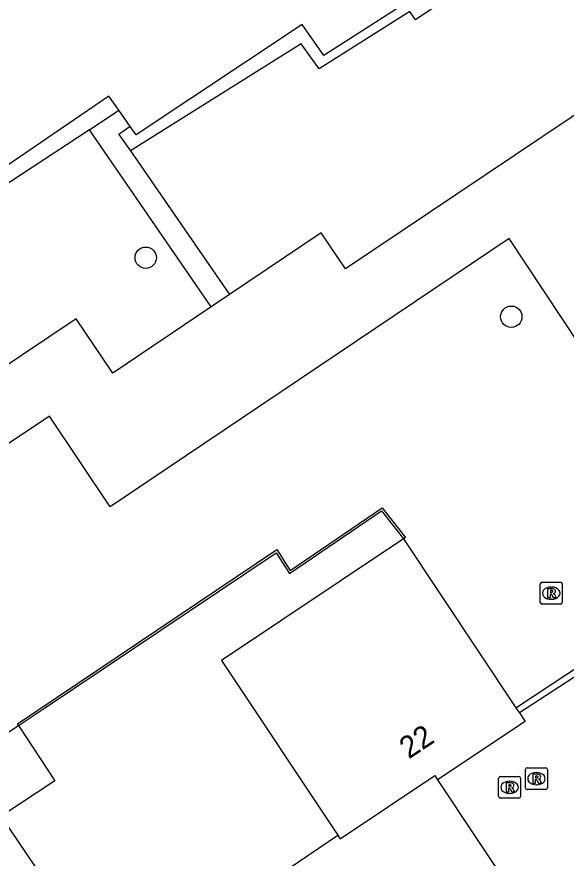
# Model space of a CAD drawing. Extents: x 158797 to 159887, y 384318 to 385255.
# Drawn here: x 158949.74 to 158974.86, y 384566.6 to 384605.03 of the extents above; entities that cross this region are included whole.
import ezdxf

# ---------------------------------------------------------------- set-up
doc = ezdxf.new("R2010")
doc.units = 0
for name, color, linetype in [('IMGEO_Boom', 7, 'Continuous'), ('IMGEO_Haag', 7, 'Continuous'), ('IMGEO_Hek', 7, 'Continuous'), ('IMGEO_Pand', 7, 'Continuous'), ('IMGEO_Pand_nummerreeks', 7, 'Continuous'), ('IMGEO_Rioolput', 7, 'Continuous'), ('IMGEO_Voetpad_gesloten', 7, 'Continuous'), ('IMGEO_Voetpad_open', 7, 'Continuous')]:
    doc.layers.add(name, color=color, linetype=linetype)

msp = doc.modelspace()

# ---------------------------------------------------------------- linework, layer by layer
at = {"layer": 'IMGEO_Boom'}
for centre in [(158955.638, 384594.028), (158972.345, 384591.33)]:
    msp.add_circle(centre, 0.489, dxfattribs=at)
at = {"layer": 'IMGEO_Haag'}
for points in [[(158967.471, 384605.617), (158963.772, 384603.26), (158962.785, 384604.676), (158955.192, 384599.646), (158954.921, 384600.028)], [(158967.706, 384605.269), (158963.564, 384602.657), (158962.736, 384603.801), (158954.947, 384598.907)], [(158954.401, 384600.762), (158953.943, 384601.409), (158945.185, 384595.438), (158944.644, 384596.144)], [(158953.064, 384599.873), (158944.835, 384594.486)], [(158949.825, 384572.659), (158949.77, 384572.742), (158961.624, 384580.694), (158962.235, 384579.747), (158966.437, 384582.607), (158967.504, 384581.247), (158967.425, 384581.185)], [(158949.825, 384572.659), (158951.056, 384573.478), (158961.595, 384580.554), (158962.205, 384579.606), (158966.416, 384582.472), (158967.425, 384581.185)], [(158972.561, 384573.474), (158980.537, 384578.738)], [(158980.737, 384578.44), (158972.715, 384573.244)]]:
    msp.add_lwpolyline(points, dxfattribs=at)
at = {"layer": 'IMGEO_Hek'}
msp.add_lwpolyline([(158951.056, 384573.478), (158961.595, 384580.554), (158962.205, 384579.606), (158966.416, 384582.472), (158967.425, 384581.185)], dxfattribs=at)
at = {"layer": 'IMGEO_Pand'}
for points in [[(158972.484, 384607.938), (158967.965, 384604.885), (158967.706, 384605.269)], [(158967.425, 384581.185), (158967.334, 384581.124), (158959.094, 384575.635), (158964.417, 384567.646)], [(158967.425, 384581.185), (158972.561, 384573.474)], [(158972.561, 384573.474), (158972.71, 384573.251), (158972.715, 384573.244)], [(158972.715, 384573.244), (158972.98, 384572.846), (158968.969, 384570.174)], [(158949.053, 384568.535), (158947.394, 384571.063), (158949.825, 384572.659)], [(158949.825, 384572.659), (158951.484, 384570.131), (158949.053, 384568.535)], [(158964.417, 384567.646), (158964.528, 384567.481), (158968.844, 384570.38), (158968.969, 384570.174)], [(158968.969, 384570.174), (158974.292, 384562.184)], [(158974.292, 384562.184), (158972.943, 384561.285), (158965.971, 384556.642), (158960.393, 384564.934), (158964.417, 384567.646)]]:
    msp.add_lwpolyline(points, dxfattribs=at)
at = {"layer": 'IMGEO_Rioolput'}
for p, q in [((158973.746, 384579.206), (158974.598, 384579.206)), ((158973.671, 384578.28), (158973.671, 384579.132)), ((158974.159, 384578.986), (158974.184, 384578.986)), ((158974.672, 384579.132), (158974.672, 384578.28)), ((158974.598, 384578.206), (158973.746, 384578.206)), ((158974.182, 384578.426), (158974.157, 384578.426)), ((158972.995, 384569.808), (158972.995, 384570.66)), ((158973.07, 384570.734), (158973.922, 384570.734)), ((158973.483, 384570.514), (158973.508, 384570.514)), ((158973.996, 384570.66), (158973.996, 384569.808)), ((158971.769, 384569.412), (158971.769, 384570.264)), ((158971.844, 384570.338), (158972.696, 384570.338)), ((158972.257, 384570.118), (158972.282, 384570.118)), ((158972.77, 384570.264), (158972.77, 384569.412)), ((158973.922, 384569.734), (158973.07, 384569.734)), ((158973.506, 384569.954), (158973.481, 384569.954)), ((158972.696, 384569.338), (158971.844, 384569.338)), ((158972.28, 384569.558), (158972.255, 384569.558))]:
    msp.add_line(p, q, dxfattribs=at)
for points in [[(158973.746, 384579.206), (158974.598, 384579.206)], [(158973.671, 384578.28), (158973.671, 384579.132)], [(158974.26, 384578.904), (158974.008, 384578.906), (158974.008, 384578.506)], [(158974.186, 384578.825), (158974.132, 384578.825), (158974.132, 384578.744)], [(158974.672, 384579.132), (158974.672, 384578.28)], [(158974.008, 384578.506), (158974.132, 384578.506), (158974.132, 384578.668), (158974.143, 384578.668)], [(158974.132, 384578.744), (158974.184, 384578.744)], [(158974.19, 384578.639), (158974.261, 384578.506), (158974.401, 384578.506), (158974.336, 384578.632)], [(158974.598, 384578.206), (158973.746, 384578.206)], [(158972.995, 384569.808), (158972.995, 384570.66)], [(158973.07, 384570.734), (158973.922, 384570.734)], [(158973.584, 384570.432), (158973.332, 384570.434), (158973.332, 384570.034)], [(158973.996, 384570.66), (158973.996, 384569.808)], [(158971.769, 384569.412), (158971.769, 384570.264)], [(158971.844, 384570.338), (158972.696, 384570.338)], [(158972.358, 384570.036), (158972.106, 384570.038), (158972.106, 384569.638)], [(158972.77, 384570.264), (158972.77, 384569.412)], [(158973.332, 384570.034), (158973.456, 384570.034), (158973.456, 384570.196), (158973.467, 384570.196)], [(158973.51, 384570.353), (158973.456, 384570.353), (158973.456, 384570.272)], [(158973.456, 384570.272), (158973.508, 384570.272)], [(158973.514, 384570.167), (158973.585, 384570.034), (158973.725, 384570.034), (158973.66, 384570.16)], [(158972.106, 384569.638), (158972.23, 384569.638), (158972.23, 384569.8), (158972.241, 384569.8)], [(158972.284, 384569.957), (158972.23, 384569.957), (158972.23, 384569.876)], [(158972.23, 384569.876), (158972.282, 384569.876)], [(158972.288, 384569.771), (158972.359, 384569.638), (158972.499, 384569.638), (158972.434, 384569.764)], [(158973.922, 384569.734), (158973.07, 384569.734)], [(158972.696, 384569.338), (158971.844, 384569.338)]]:
    msp.add_lwpolyline(points, dxfattribs=at)
for centre, radius, start, end in [((158973.748, 384579.13), 0.0765, 91.552, 178.448), ((158973.748, 384579.13), 0.0765, 91.552, 178.448), ((158974.596, 384579.13), 0.0765, 1.552, 88.448), ((158974.596, 384579.13), 0.0765, 1.552, 88.448), ((158974.192, 384578.729), 0.0964, 77.0061, 93.1865), ((158974.206, 384578.786), 0.0378, 276.6634, 79.6772), ((158974.259, 384578.794), 0.109, 350.3612, 89.416), ((158974.142, 384578.615), 0.0533, 26.0293, 88.6989), ((158974.168, 384578.933), 0.19, 274.7715, 282.9687), ((158974.257, 384578.794), 0.112, 277.5842, 350.9817), ((158974.241, 384578.579), 0.108, 29.5134, 73.7905), ((158973.748, 384578.282), 0.0765, 181.552, 268.448), ((158973.748, 384578.282), 0.0765, 181.552, 268.448), ((158974.596, 384578.282), 0.0765, 271.552, 358.448), ((158974.596, 384578.282), 0.0765, 271.552, 358.448), ((158973.072, 384570.658), 0.0765, 91.552, 178.448), ((158973.072, 384570.658), 0.0765, 91.552, 178.448), ((158973.583, 384570.322), 0.109, 350.3612, 89.416), ((158973.92, 384570.658), 0.0765, 1.552, 88.448), ((158973.92, 384570.658), 0.0765, 1.552, 88.448), ((158971.846, 384570.262), 0.0765, 91.552, 178.448), ((158971.846, 384570.262), 0.0765, 91.552, 178.448), ((158972.357, 384569.926), 0.109, 350.3612, 89.416), ((158972.694, 384570.262), 0.0765, 1.552, 88.448), ((158972.694, 384570.262), 0.0765, 1.552, 88.448), ((158973.466, 384570.143), 0.0533, 26.0293, 88.6989), ((158973.492, 384570.461), 0.19, 274.7715, 282.9687), ((158973.516, 384570.257), 0.0964, 77.0061, 93.1865), ((158973.53, 384570.314), 0.0378, 276.6634, 79.6772), ((158973.581, 384570.322), 0.112, 277.5842, 350.9817), ((158973.565, 384570.107), 0.108, 29.5134, 73.7905), ((158972.24, 384569.747), 0.0533, 26.0293, 88.6989), ((158972.266, 384570.065), 0.19, 274.7715, 282.9687), ((158972.29, 384569.861), 0.0964, 77.0061, 93.1865), ((158972.304, 384569.918), 0.0378, 276.6634, 79.6772), ((158972.355, 384569.926), 0.112, 277.5842, 350.9817), ((158972.339, 384569.711), 0.108, 29.5134, 73.7905), ((158973.072, 384569.81), 0.0765, 181.552, 268.448), ((158973.072, 384569.81), 0.0765, 181.552, 268.448), ((158973.92, 384569.81), 0.0765, 271.552, 358.448), ((158973.92, 384569.81), 0.0765, 271.552, 358.448), ((158971.846, 384569.414), 0.0765, 181.552, 268.448), ((158971.846, 384569.414), 0.0765, 181.552, 268.448), ((158972.694, 384569.414), 0.0765, 271.552, 358.448), ((158972.694, 384569.414), 0.0765, 271.552, 358.448)]:
    msp.add_arc(centre, radius, start, end, dxfattribs=at)
for centre, major_axis, ratio, start_param, end_param in [((158974.158, 384578.706), (-0.387, 0.002), 0.722429, 4.712389, 7.853982), ((158974.183, 384578.706), (-0.39, 0.002), 0.717154, 1.570796, 4.712389), ((158973.482, 384570.234), (-0.387, 0.002), 0.722429, 4.712389, 7.853982), ((158973.507, 384570.234), (-0.39, 0.002), 0.717154, 1.570796, 4.712389), ((158972.256, 384569.838), (-0.387, 0.002), 0.722429, 4.712389, 7.853982), ((158972.281, 384569.838), (-0.39, 0.002), 0.717154, 1.570796, 4.712389)]:
    msp.add_ellipse(centre, major_axis=major_axis, ratio=ratio, start_param=start_param, end_param=end_param, dxfattribs=at)
at = {"layer": 'IMGEO_Voetpad_gesloten'}
for points in [[(158986.075, 384615.399), (158991.291, 384607.705), (158978.032, 384598.831), (158976.371, 384601.302), (158964.769, 384593.518), (158963.656, 384595.17), (158959.461, 384592.344)], [(158984.514, 384583.901), (158981.067, 384581.606), (158972.244, 384594.899), (158954.016, 384582.655), (158951.236, 384586.787), (158946.678, 384583.765), (158946.282, 384584.317), (158942.972, 384582.114), (158943.515, 384581.292), (158938.423, 384577.854)], [(158959.461, 384592.344), (158958.622, 384591.779)], [(158958.622, 384591.779), (158954.136, 384588.758), (158952.459, 384591.238), (158948.689, 384588.717)]]:
    msp.add_lwpolyline(points, dxfattribs=at)
at = {"layer": 'IMGEO_Voetpad_open'}
for points in [[(158953.064, 384599.873), (158954.401, 384600.762)], [(158954.921, 384600.028), (158954.401, 384600.762)], [(158954.921, 384600.028), (158954.403, 384599.659), (158954.947, 384598.907)], [(158958.622, 384591.779), (158953.064, 384599.873)], [(158954.947, 384598.907), (158959.461, 384592.344)], [(158951.765, 384563.716), (158952.121, 384563.96), (158949.042, 384568.513)]]:
    msp.add_lwpolyline(points, dxfattribs=at)

# ---------------------------------------------------------------- texts
at = {"layer": 'IMGEO_Pand_nummerreeks'}
msp.add_text('22', height=1, rotation=33.6727, dxfattribs=at).set_placement((158967.662, 384571.106))

doc.saveas('drawing.dxf')
